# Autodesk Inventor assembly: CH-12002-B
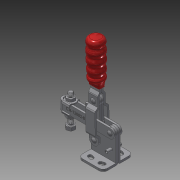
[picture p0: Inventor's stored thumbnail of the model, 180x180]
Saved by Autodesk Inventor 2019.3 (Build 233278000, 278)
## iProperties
Company: Î¢ÈíÖÐ¹ú
Created: 2012-09
Part Number: CH-12002-B
Material: Ogólny
Description: STEP AP203
Document SubType Name: Assembly
Designer: CADENGINEERING4
Stock Number: DOCISK PIONOWY
Sending System: SolidWorks 2010
Preprocessor: SwSTEP 2.0
Title: CH-12002-B.STEP
Author: Î¢ÈíÓÃ»§
Revision Number: ÈÎºÎ
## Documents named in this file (11)
- D:\Vault_2016\Projekty\Clamptek\STRONA\Vertical toggle clamp\CH-12002-B\CH-12002-B_ZAMKNIETY.iam
- D:\Vault_2016\Projekty\Clamptek\STRONA\Vertical toggle clamp\CH-12002-B\M6 Nut.ipt
- D:\Vault_2016\Projekty\Clamptek\STRONA\Vertical toggle clamp\CH-12002-B\CH-12002-B-02 U-BAR.ipt
- D:\Vault_2016\Projekty\Clamptek\STRONA\Vertical toggle clamp\CH-12002-B\CH-12002-B-06.ipt
- D:\Vault_2016\Projekty\Clamptek\STRONA\Vertical toggle clamp\CH-12002-B\CH-12002-B-01 FLANGED BASE.ipt
- D:\Vault_2016\Projekty\Clamptek\STRONA\Vertical toggle clamp\CH-12002-B\CH-FW-140.ipt
- D:\Vault_2016\Projekty\Clamptek\STRONA\Vertical toggle clamp\CH-12002-B\CH-SA-064010 SPINDLE SUPPLIED.ipt
- D:\Vault_2016\Projekty\Clamptek\STRONA\Vertical toggle clamp\CH-12002-B\CH-12002-B-07.ipt
- D:\Vault_2016\Projekty\Clamptek\STRONA\Vertical toggle clamp\CH-12002-B\CH-12002-B-04 CONNECTING-PLATE.ipt
- D:\Vault_2016\Projekty\Clamptek\STRONA\Vertical toggle clamp\CH-12002-B\CH-12002-B-05.ipt
- D:\Vault_2016\Projekty\Clamptek\STRONA\Vertical toggle clamp\CH-12002-B\CH-12002-B-03 HANDLE.ipt
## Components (15 placed, 15 different names)
1. M6 Nut_1
2. CH-12002-B-02 U-BAR_2
3. CH-12002-B-06_3
4. CH-12002-B-01 FLANGED BASE_4
5. M6 Nut_5
6. CH-FW-140_6
7. CH-SA-064010 SPINDLE SUPPLIED_7
8. CH-12002-B-07_8
9. CH-12002-B-06_9
10. CH-12002-B-04 CONNECTING-PLATE_10
11. CH-FW-140_11
12. CH-12002-B-06_12
13. CH-12002-B-06_13
14. CH-12002-B-05_14
15. CH-12002-B-03 HANDLE_15
